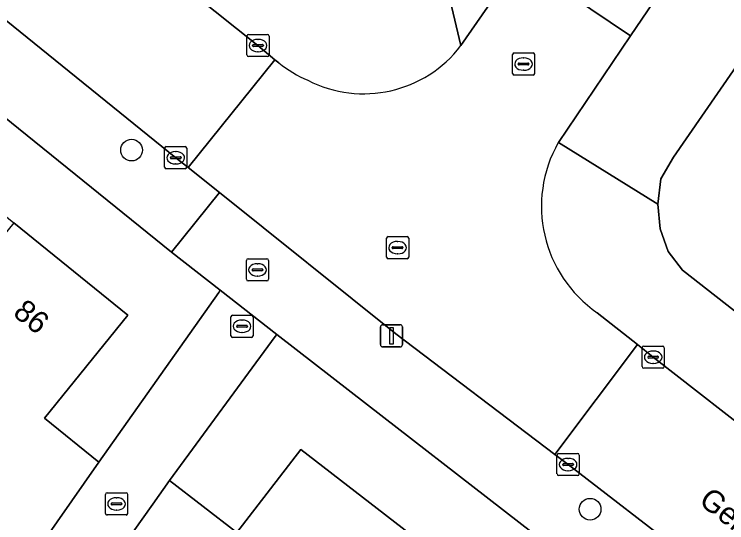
# Model space of a CAD drawing. Extents: x 160157 to 160921, y 381516 to 382045.
# Drawn here: x 160586.64 to 160618.81, y 381662.86 to 381685.82 of the extents above; entities that cross this region are included whole.
import ezdxf

# ---------------------------------------------------------------- set-up
doc = ezdxf.new("R2010")
doc.units = 0
for name, color, linetype in [('IMGEO_Boom', 7, 'Continuous'), ('IMGEO_Brandkraan', 7, 'Continuous'), ('IMGEO_Erf', 7, 'Continuous'), ('IMGEO_Kolk', 7, 'Continuous'), ('IMGEO_Lichtmast', 7, 'Continuous'), ('IMGEO_Openbare_ruimte_label', 7, 'Continuous'), ('IMGEO_Pand', 7, 'Continuous'), ('IMGEO_Pand_nummerreeks', 7, 'Continuous'), ('IMGEO_Rijbaan_lokaal_open', 7, 'Continuous'), ('IMGEO_Rioolput', 7, 'Continuous'), ('IMGEO_Voetpad_open', 7, 'Continuous')]:
    doc.layers.add(name, color=color, linetype=linetype)

msp = doc.modelspace()

# ---------------------------------------------------------------- linework, layer by layer
at = {"layer": 'IMGEO_Boom'}
for centre in [(160591.934, 381679.684), (160612.638, 381663.471)]:
    msp.add_circle(centre, 0.489, dxfattribs=at)
at = {"layer": 'IMGEO_Brandkraan'}
for p, q in [((160597.12, 381673.85), (160597.12, 381674.702)), ((160597.195, 381674.776), (160598.047, 381674.776)), ((160598.121, 381674.702), (160598.121, 381673.85)), ((160597.422, 381674.319), (160597.82, 381674.319)), ((160597.608, 381674.556), (160597.633, 381674.556)), ((160597.379, 381674.27), (160597.379, 381674.282)), ((160597.817, 381674.233), (160597.419, 381674.233)), ((160597.631, 381673.996), (160597.606, 381673.996)), ((160597.863, 381674.282), (160597.863, 381674.27)), ((160598.047, 381673.776), (160597.195, 381673.776))]:
    msp.add_line(p, q, dxfattribs=at)
for points in [[(160597.12, 381673.85), (160597.12, 381674.702)], [(160597.195, 381674.776), (160598.047, 381674.776)], [(160598.121, 381674.702), (160598.121, 381673.85)], [(160598.047, 381673.776), (160597.195, 381673.776)]]:
    msp.add_lwpolyline(points, dxfattribs=at)
for centre, radius, start, end in [((160597.197, 381674.7), 0.0765, 91.552, 178.448), ((160597.197, 381674.7), 0.0765, 91.552, 178.448), ((160598.045, 381674.7), 0.0765, 1.552, 88.448), ((160598.045, 381674.7), 0.0765, 1.552, 88.448), ((160597.419, 381674.279), 0.0403, 85.8775, 175.7526), ((160597.824, 381674.281), 0.0386, 1.7309, 96.639), ((160597.416, 381674.269), 0.0366, 178.938, 274.7102), ((160597.82, 381674.276), 0.043, 264.8664, 352.4533), ((160597.197, 381673.852), 0.0765, 181.552, 268.448), ((160597.197, 381673.852), 0.0765, 181.552, 268.448), ((160598.045, 381673.852), 0.0765, 271.552, 358.448), ((160598.045, 381673.852), 0.0765, 271.552, 358.448)]:
    msp.add_arc(centre, radius, start, end, dxfattribs=at)
for centre, major_axis, ratio, start_param, end_param in [((160597.607, 381674.276), (-0.387, 0.002), 0.722429, 4.712389, 7.853982), ((160597.632, 381674.276), (-0.39, 0.002), 0.717154, 1.570796, 4.712389)]:
    msp.add_ellipse(centre, major_axis=major_axis, ratio=ratio, start_param=start_param, end_param=end_param, dxfattribs=at)
at = {"layer": 'IMGEO_Erf'}
for points in [[(160644.455, 381719.97), (160616.408, 381679.37), (160615.835, 381678.381), (160615.694, 381677.246), (160615.808, 381676.128), (160616.155, 381675.113), (160616.813, 381674.266), (160634.918, 381660.1)], [(160652.939, 381629.15), (160652.772, 381629.282), (160601.85, 381668.749), (160598.492, 381671.366), (160598.418, 381671.265), (160593.646, 381664.765), (160596.685, 381662.418), (160599.574, 381666.16), (160604.808, 381662.117), (160609.913, 381658.174), (160615.018, 381654.231), (160620.122, 381650.288), (160625.226, 381646.346), (160630.458, 381642.305), (160628.484, 381639.75), (160630.816, 381637.948), (160632.401, 381640), (160640.628, 381633.646), (160639.436, 381632.103), (160647.232, 381626.081)]]:
    msp.add_lwpolyline(points, dxfattribs=at)
msp.add_lwpolyline([(160558.545, 381703.514), (160556.409, 381700.887), (160561.559, 381696.713), (160566.569, 381692.651), (160571.58, 381688.589), (160576.591, 381684.528), (160581.601, 381680.467), (160586.612, 381676.405), (160591.761, 381672.231), (160587.997, 381667.587), (160590.45, 381665.598), (160595.868, 381673.258), (160595.937, 381673.356), (160593.737, 381675.072)], close=True, dxfattribs=at)
at = {"layer": 'IMGEO_Kolk'}
for p, q in [((160597.141, 381683.978), (160597.141, 381684.83)), ((160597.216, 381684.904), (160598.068, 381684.904)), ((160597.629, 381684.684), (160597.654, 381684.684)), ((160598.142, 381684.83), (160598.142, 381683.978)), ((160597.4, 381684.398), (160597.4, 381684.41)), ((160597.838, 381684.361), (160597.44, 381684.361)), ((160597.443, 381684.447), (160597.841, 381684.447)), ((160597.884, 381684.41), (160597.884, 381684.398)), ((160597.652, 381684.124), (160597.627, 381684.124)), ((160598.068, 381683.904), (160597.216, 381683.904)), ((160593.427, 381678.913), (160593.427, 381679.765)), ((160593.502, 381679.839), (160594.354, 381679.839)), ((160594.428, 381679.765), (160594.428, 381678.913)), ((160593.915, 381679.619), (160593.94, 381679.619)), ((160593.686, 381679.333), (160593.686, 381679.345)), ((160594.124, 381679.296), (160593.726, 381679.296)), ((160593.729, 381679.382), (160594.127, 381679.382)), ((160594.17, 381679.345), (160594.17, 381679.333)), ((160594.354, 381678.839), (160593.502, 381678.839)), ((160593.938, 381679.059), (160593.913, 381679.059)), ((160614.987, 381669.908), (160614.987, 381670.76)), ((160615.062, 381670.834), (160615.914, 381670.834)), ((160615.988, 381670.76), (160615.988, 381669.908)), ((160615.475, 381670.614), (160615.5, 381670.614)), ((160615.246, 381670.328), (160615.246, 381670.34)), ((160615.684, 381670.291), (160615.286, 381670.291)), ((160615.289, 381670.377), (160615.687, 381670.377)), ((160615.73, 381670.34), (160615.73, 381670.328)), ((160615.914, 381669.834), (160615.062, 381669.834)), ((160615.498, 381670.054), (160615.473, 381670.054)), ((160611.217, 381665.988), (160612.069, 381665.988)), ((160611.142, 381665.062), (160611.142, 381665.914)), ((160611.63, 381665.768), (160611.655, 381665.768)), ((160612.143, 381665.914), (160612.143, 381665.062)), ((160611.401, 381665.482), (160611.401, 381665.494)), ((160611.839, 381665.445), (160611.441, 381665.445)), ((160611.444, 381665.531), (160611.842, 381665.531)), ((160611.885, 381665.494), (160611.885, 381665.482)), ((160612.069, 381664.988), (160611.217, 381664.988)), ((160611.653, 381665.208), (160611.628, 381665.208)), ((160590.756, 381663.284), (160590.756, 381664.136)), ((160590.831, 381664.21), (160591.683, 381664.21)), ((160591.757, 381664.136), (160591.757, 381663.284)), ((160591.015, 381663.704), (160591.015, 381663.716)), ((160591.058, 381663.753), (160591.456, 381663.753)), ((160591.244, 381663.99), (160591.269, 381663.99)), ((160591.499, 381663.716), (160591.499, 381663.704)), ((160591.453, 381663.667), (160591.055, 381663.667)), ((160591.267, 381663.43), (160591.242, 381663.43)), ((160591.683, 381663.21), (160590.831, 381663.21))]:
    msp.add_line(p, q, dxfattribs=at)
for points in [[(160597.141, 381683.978), (160597.141, 381684.83)], [(160597.216, 381684.904), (160598.068, 381684.904)], [(160598.142, 381684.83), (160598.142, 381683.978)], [(160598.068, 381683.904), (160597.216, 381683.904)], [(160593.427, 381678.913), (160593.427, 381679.765)], [(160593.502, 381679.839), (160594.354, 381679.839)], [(160594.428, 381679.765), (160594.428, 381678.913)], [(160594.354, 381678.839), (160593.502, 381678.839)], [(160614.987, 381669.908), (160614.987, 381670.76)], [(160615.062, 381670.834), (160615.914, 381670.834)], [(160615.988, 381670.76), (160615.988, 381669.908)], [(160615.914, 381669.834), (160615.062, 381669.834)], [(160611.217, 381665.988), (160612.069, 381665.988)], [(160611.142, 381665.062), (160611.142, 381665.914)], [(160612.143, 381665.914), (160612.143, 381665.062)], [(160612.069, 381664.988), (160611.217, 381664.988)], [(160590.756, 381663.284), (160590.756, 381664.136)], [(160590.831, 381664.21), (160591.683, 381664.21)], [(160591.757, 381664.136), (160591.757, 381663.284)], [(160591.683, 381663.21), (160590.831, 381663.21)]]:
    msp.add_lwpolyline(points, dxfattribs=at)
for centre, radius, start, end in [((160597.218, 381684.828), 0.0765, 91.552, 178.448), ((160597.218, 381684.828), 0.0765, 91.552, 178.448), ((160598.066, 381684.828), 0.0765, 1.552, 88.448), ((160598.066, 381684.828), 0.0765, 1.552, 88.448), ((160597.44, 381684.407), 0.0403, 85.8775, 175.7526), ((160597.437, 381684.397), 0.0366, 178.938, 274.7102), ((160597.841, 381684.404), 0.043, 264.8664, 352.4533), ((160597.845, 381684.409), 0.0386, 1.7309, 96.639), ((160597.218, 381683.98), 0.0765, 181.552, 268.448), ((160597.218, 381683.98), 0.0765, 181.552, 268.448), ((160598.066, 381683.98), 0.0765, 271.552, 358.448), ((160598.066, 381683.98), 0.0765, 271.552, 358.448), ((160593.504, 381679.763), 0.0765, 91.552, 178.448), ((160593.504, 381679.763), 0.0765, 91.552, 178.448), ((160594.352, 381679.763), 0.0765, 1.552, 88.448), ((160594.352, 381679.763), 0.0765, 1.552, 88.448), ((160593.726, 381679.342), 0.0403, 85.8775, 175.7526), ((160593.723, 381679.332), 0.0366, 178.938, 274.7102), ((160594.127, 381679.339), 0.043, 264.8664, 352.4533), ((160594.131, 381679.344), 0.0386, 1.7309, 96.639), ((160593.504, 381678.915), 0.0765, 181.552, 268.448), ((160593.504, 381678.915), 0.0765, 181.552, 268.448), ((160594.352, 381678.915), 0.0765, 271.552, 358.448), ((160594.352, 381678.915), 0.0765, 271.552, 358.448), ((160615.064, 381670.758), 0.0765, 91.552, 178.448), ((160615.064, 381670.758), 0.0765, 91.552, 178.448), ((160615.912, 381670.758), 0.0765, 1.552, 88.448), ((160615.912, 381670.758), 0.0765, 1.552, 88.448), ((160615.286, 381670.337), 0.0403, 85.8775, 175.7526), ((160615.283, 381670.327), 0.0366, 178.938, 274.7102), ((160615.687, 381670.334), 0.043, 264.8664, 352.4533), ((160615.691, 381670.339), 0.0386, 1.7309, 96.639), ((160615.064, 381669.91), 0.0765, 181.552, 268.448), ((160615.064, 381669.91), 0.0765, 181.552, 268.448), ((160615.912, 381669.91), 0.0765, 271.552, 358.448), ((160615.912, 381669.91), 0.0765, 271.552, 358.448), ((160611.219, 381665.912), 0.0765, 91.552, 178.448), ((160611.219, 381665.912), 0.0765, 91.552, 178.448), ((160612.067, 381665.912), 0.0765, 1.552, 88.448), ((160612.067, 381665.912), 0.0765, 1.552, 88.448), ((160611.441, 381665.491), 0.0403, 85.8775, 175.7526), ((160611.438, 381665.481), 0.0366, 178.938, 274.7102), ((160611.842, 381665.488), 0.043, 264.8664, 352.4533), ((160611.846, 381665.493), 0.0386, 1.7309, 96.639), ((160611.219, 381665.064), 0.0765, 181.552, 268.448), ((160611.219, 381665.064), 0.0765, 181.552, 268.448), ((160612.067, 381665.064), 0.0765, 271.552, 358.448), ((160612.067, 381665.064), 0.0765, 271.552, 358.448), ((160590.833, 381664.134), 0.0765, 91.552, 178.448), ((160590.833, 381664.134), 0.0765, 91.552, 178.448), ((160591.681, 381664.134), 0.0765, 1.552, 88.448), ((160591.681, 381664.134), 0.0765, 1.552, 88.448), ((160591.055, 381663.713), 0.0403, 85.8775, 175.7526), ((160591.052, 381663.703), 0.0366, 178.938, 274.7102), ((160591.456, 381663.71), 0.043, 264.8664, 352.4533), ((160591.46, 381663.715), 0.0386, 1.7309, 96.639), ((160590.833, 381663.286), 0.0765, 181.552, 268.448), ((160590.833, 381663.286), 0.0765, 181.552, 268.448), ((160591.681, 381663.286), 0.0765, 271.552, 358.448), ((160591.681, 381663.286), 0.0765, 271.552, 358.448)]:
    msp.add_arc(centre, radius, start, end, dxfattribs=at)
for centre, major_axis, ratio, start_param, end_param in [((160597.628, 381684.404), (-0.387, 0.002), 0.722429, 4.712389, 7.853982), ((160597.653, 381684.404), (-0.39, 0.002), 0.717154, 1.570796, 4.712389), ((160593.914, 381679.339), (-0.387, 0.002), 0.722429, 4.712389, 7.853982), ((160593.939, 381679.339), (-0.39, 0.002), 0.717154, 1.570796, 4.712389), ((160615.474, 381670.334), (-0.387, 0.002), 0.722429, 4.712389, 7.853982), ((160615.499, 381670.334), (-0.39, 0.002), 0.717154, 1.570796, 4.712389), ((160611.629, 381665.488), (-0.387, 0.002), 0.722429, 4.712389, 7.853982), ((160611.654, 381665.488), (-0.39, 0.002), 0.717154, 1.570796, 4.712389), ((160591.243, 381663.71), (-0.387, 0.002), 0.722429, 4.712389, 7.853982), ((160591.268, 381663.71), (-0.39, 0.002), 0.717154, 1.570796, 4.712389)]:
    msp.add_ellipse(centre, major_axis=major_axis, ratio=ratio, start_param=start_param, end_param=end_param, dxfattribs=at)
at = {"layer": 'IMGEO_Lichtmast'}
for p, q in [((160603.27, 381671.8), (160604.06, 381671.8)), ((160604.06, 381671.8), (160603.27, 381671.8)), ((160603.17, 381670.9), (160603.17, 381671.7)), ((160603.17, 381671.7), (160603.17, 381670.9)), ((160604.16, 381671.7), (160604.16, 381670.9)), ((160604.16, 381670.9), (160604.16, 381671.7)), ((160604.06, 381670.8), (160603.27, 381670.8)), ((160603.27, 381670.8), (160604.06, 381670.8))]:
    msp.add_line(p, q, dxfattribs=at)
msp.add_lwpolyline([(160603.59, 381671.675), (160603.74, 381671.675), (160603.74, 381670.925), (160603.59, 381670.925), (160603.59, 381671.675)], dxfattribs=at)
for centre, start, end in [((160603.27, 381671.7), 90, 180), ((160603.27, 381671.7), 90, 180), ((160604.06, 381671.7), 0, 90), ((160604.06, 381671.7), 360, 90), ((160603.27, 381670.9), 180, 270), ((160603.27, 381670.9), 180, 270), ((160604.06, 381670.9), 270, 0), ((160604.06, 381670.9), 270, 0)]:
    msp.add_arc(centre, 0.1, start, end, dxfattribs=at)
at = {"layer": 'IMGEO_Pand'}
for points in [[(160580.438, 381668.789), (160582.556, 381667.072), (160582.916, 381667.516), (160585.732, 381665.217), (160583.705, 381662.628), (160586.695, 381660.204), (160590.45, 381665.598), (160587.997, 381667.587), (160591.761, 381672.231), (160586.612, 381676.405)], [(160604.808, 381662.117), (160599.574, 381666.16), (160596.685, 381662.418), (160593.646, 381664.765), (160592.891, 381663.696), (160589.08, 381658.343), (160588.551, 381657.587), (160593.872, 381653.476), (160596.57, 381656.969), (160599.239, 381654.908)]]:
    msp.add_lwpolyline(points, close=True, dxfattribs=at)
at = {"layer": 'IMGEO_Rijbaan_lokaal_open'}
for points in [[(160678.334, 381788.56), (160651.806, 381750), (160643.136, 381737.367), (160641.13, 381734.448), (160614.441, 381695.549), (160610.996, 381690.462), (160609.452, 381688.229), (160609.962, 381687.883), (160614.454, 381684.835), (160615.999, 381687.121), (160619.05, 381691.582), (160640.187, 381722.521), (160642.496, 381725.9), (160658.96, 381750), (160667.503, 381762.414)], [(160614.454, 381684.835), (160609.962, 381687.883), (160609.452, 381688.229), (160606.806, 381684.4)], [(160611.203, 381680.025), (160614.454, 381684.835)], [(160598.577, 381683.621), (160598.404, 381683.766), (160594.486, 381678.894), (160595.897, 381677.768), (160603.873, 381671.389), (160611.044, 381665.943), (160614.775, 381670.9), (160612.96, 381672.341)], [(160589.08, 381658.343), (160592.891, 381663.696), (160593.646, 381664.765), (160598.418, 381671.265), (160598.492, 381671.366), (160595.937, 381673.356), (160595.868, 381673.258), (160590.45, 381665.598), (160586.695, 381660.204)]]:
    msp.add_lwpolyline(points, dxfattribs=at)
for points in [[(160568.758, 381707.591), (160557.554, 381716.59), (160557.502, 381716.634), (160557.472, 381716.661), (160550.945, 381722.011), (160550.931, 381722.022), (160550.918, 381722.034), (160550.145, 381722.678), (160546.247, 381717.93), (160547.02, 381717.298), (160547.066, 381717.257), (160553.47, 381712.091), (160558.948, 381707.655), (160565.145, 381702.637), (160577.959, 381692.258), (160593.928, 381679.339), (160594.486, 381678.894), (160598.404, 381683.766), (160597.642, 381684.404), (160592.745, 381688.322), (160581.553, 381697.274)], [(160637.757, 381653.019), (160629.795, 381659.181), (160625.991, 381662.142), (160615.488, 381670.334), (160614.775, 381670.9), (160611.044, 381665.943), (160611.643, 381665.488), (160622.338, 381657.247), (160634.337, 381647.947), (160640.783, 381642.937), (160653.969, 381632.702), (160654.563, 381632.216), (160655.367, 381631.558), (160659.031, 381636.532), (160658.192, 381637.172), (160657.666, 381637.573), (160640.627, 381650.806)]]:
    msp.add_lwpolyline(points, close=True, dxfattribs=at)
for centre, radius, start, end in [((160602.412, 381687.757), 5.53, 242.9032, 322.6244), ((160602.286, 381688.33), 5.995, 231.7715, 246.4676), ((160616.274, 381677.142), 5.834, 150.3803, 235.379)]:
    msp.add_arc(centre, radius, start, end, dxfattribs=at)
at = {"layer": 'IMGEO_Rioolput'}
for p, q in [((160609.133, 381683.144), (160609.133, 381683.996)), ((160609.208, 381684.07), (160610.06, 381684.07)), ((160610.134, 381683.996), (160610.134, 381683.144)), ((160609.621, 381683.85), (160609.646, 381683.85)), ((160609.392, 381683.564), (160609.392, 381683.576)), ((160609.83, 381683.527), (160609.432, 381683.527)), ((160609.435, 381683.613), (160609.833, 381683.613)), ((160609.876, 381683.576), (160609.876, 381683.564)), ((160610.06, 381683.07), (160609.208, 381683.07)), ((160609.644, 381683.29), (160609.619, 381683.29)), ((160603.444, 381674.854), (160603.444, 381675.706)), ((160603.519, 381675.78), (160604.371, 381675.78)), ((160604.445, 381675.706), (160604.445, 381674.854)), ((160603.703, 381675.274), (160603.703, 381675.286)), ((160603.746, 381675.323), (160604.144, 381675.323)), ((160603.932, 381675.56), (160603.957, 381675.56)), ((160604.187, 381675.286), (160604.187, 381675.274)), ((160604.141, 381675.237), (160603.743, 381675.237)), ((160603.955, 381675), (160603.93, 381675)), ((160604.371, 381674.78), (160603.519, 381674.78)), ((160596.421, 381671.304), (160596.421, 381672.156)), ((160596.496, 381672.23), (160597.348, 381672.23)), ((160597.422, 381672.156), (160597.422, 381671.304)), ((160596.68, 381671.724), (160596.68, 381671.736)), ((160596.723, 381671.773), (160597.121, 381671.773)), ((160596.909, 381672.01), (160596.934, 381672.01)), ((160597.164, 381671.736), (160597.164, 381671.724)), ((160597.118, 381671.687), (160596.72, 381671.687)), ((160596.932, 381671.45), (160596.907, 381671.45)), ((160597.348, 381671.23), (160596.496, 381671.23))]:
    msp.add_line(p, q, dxfattribs=at)
for points in [[(160609.133, 381683.144), (160609.133, 381683.996)], [(160609.208, 381684.07), (160610.06, 381684.07)], [(160610.134, 381683.996), (160610.134, 381683.144)], [(160610.06, 381683.07), (160609.208, 381683.07)], [(160603.444, 381674.854), (160603.444, 381675.706)], [(160603.519, 381675.78), (160604.371, 381675.78)], [(160604.445, 381675.706), (160604.445, 381674.854)], [(160604.371, 381674.78), (160603.519, 381674.78)], [(160596.421, 381671.304), (160596.421, 381672.156)], [(160596.496, 381672.23), (160597.348, 381672.23)], [(160597.422, 381672.156), (160597.422, 381671.304)], [(160597.348, 381671.23), (160596.496, 381671.23)]]:
    msp.add_lwpolyline(points, dxfattribs=at)
for centre, radius, start, end in [((160609.21, 381683.994), 0.0765, 91.552, 178.448), ((160609.21, 381683.994), 0.0765, 91.552, 178.448), ((160610.058, 381683.994), 0.0765, 1.552, 88.448), ((160610.058, 381683.994), 0.0765, 1.552, 88.448), ((160609.432, 381683.573), 0.0403, 85.8775, 175.7526), ((160609.429, 381683.563), 0.0366, 178.938, 274.7102), ((160609.833, 381683.57), 0.043, 264.8664, 352.4533), ((160609.837, 381683.575), 0.0386, 1.7309, 96.639), ((160609.21, 381683.146), 0.0765, 181.552, 268.448), ((160609.21, 381683.146), 0.0765, 181.552, 268.448), ((160610.058, 381683.146), 0.0765, 271.552, 358.448), ((160610.058, 381683.146), 0.0765, 271.552, 358.448), ((160603.521, 381675.704), 0.0765, 91.552, 178.448), ((160603.521, 381675.704), 0.0765, 91.552, 178.448), ((160604.369, 381675.704), 0.0765, 1.552, 88.448), ((160604.369, 381675.704), 0.0765, 1.552, 88.448), ((160603.743, 381675.283), 0.0403, 85.8775, 175.7526), ((160603.74, 381675.273), 0.0366, 178.938, 274.7102), ((160604.144, 381675.28), 0.043, 264.8664, 352.4533), ((160604.148, 381675.285), 0.0386, 1.7309, 96.639), ((160603.521, 381674.856), 0.0765, 181.552, 268.448), ((160603.521, 381674.856), 0.0765, 181.552, 268.448), ((160604.369, 381674.856), 0.0765, 271.552, 358.448), ((160604.369, 381674.856), 0.0765, 271.552, 358.448), ((160596.498, 381672.154), 0.0765, 91.552, 178.448), ((160596.498, 381672.154), 0.0765, 91.552, 178.448), ((160597.346, 381672.154), 0.0765, 1.552, 88.448), ((160597.346, 381672.154), 0.0765, 1.552, 88.448), ((160596.72, 381671.733), 0.0403, 85.8775, 175.7526), ((160596.717, 381671.723), 0.0366, 178.938, 274.7102), ((160597.121, 381671.73), 0.043, 264.8664, 352.4533), ((160597.125, 381671.735), 0.0386, 1.7309, 96.639), ((160596.498, 381671.306), 0.0765, 181.552, 268.448), ((160596.498, 381671.306), 0.0765, 181.552, 268.448), ((160597.346, 381671.306), 0.0765, 271.552, 358.448), ((160597.346, 381671.306), 0.0765, 271.552, 358.448)]:
    msp.add_arc(centre, radius, start, end, dxfattribs=at)
for centre, major_axis, ratio, start_param, end_param in [((160609.62, 381683.57), (-0.387, 0.002), 0.722429, 4.712389, 7.853982), ((160609.645, 381683.57), (-0.39, 0.002), 0.717154, 1.570796, 4.712389), ((160603.931, 381675.28), (-0.387, 0.002), 0.722429, 4.712389, 7.853982), ((160603.956, 381675.28), (-0.39, 0.002), 0.717154, 1.570796, 4.712389), ((160596.908, 381671.73), (-0.387, 0.002), 0.722429, 4.712389, 7.853982), ((160596.933, 381671.73), (-0.39, 0.002), 0.717154, 1.570796, 4.712389)]:
    msp.add_ellipse(centre, major_axis=major_axis, ratio=ratio, start_param=start_param, end_param=end_param, dxfattribs=at)
at = {"layer": 'IMGEO_Voetpad_open'}
for points in [[(160707.501, 381830.956), (160711.08, 381836.076), (160711.248, 381836.325), (160707.078, 381835.076), (160693.176, 381814.897), (160692.079, 381813.304), (160675.928, 381789.86), (160675.328, 381788.989), (160648.467, 381750), (160641.671, 381740.128), (160640.592, 381738.561), (160605.905, 381688.17), (160606.806, 381684.4), (160609.452, 381688.229), (160610.996, 381690.462), (160614.441, 381695.549), (160641.13, 381734.448), (160643.136, 381737.367), (160651.806, 381750), (160678.334, 381788.56), (160680.332, 381791.464), (160692.328, 381808.901), (160699.651, 381819.545)], [(160603.873, 381671.389), (160595.897, 381677.768), (160593.737, 381675.072), (160595.937, 381673.356), (160598.492, 381671.366), (160601.85, 381668.749), (160652.772, 381629.282), (160652.939, 381629.15), (160655.367, 381631.558), (160654.563, 381632.216), (160653.969, 381632.702), (160640.783, 381642.937), (160634.337, 381647.947), (160622.338, 381657.247), (160611.643, 381665.488), (160611.044, 381665.943)]]:
    msp.add_lwpolyline(points, close=True, dxfattribs=at)
for points in [[(160716.089, 381833.009), (160716.028, 381832.837), (160712.504, 381827.801), (160703.573, 381814.824), (160700.524, 381810.394), (160670.296, 381766.471), (160667.503, 381762.414), (160658.96, 381750), (160642.496, 381725.9), (160640.187, 381722.521), (160619.05, 381691.582), (160615.999, 381687.121), (160614.454, 381684.835), (160611.203, 381680.025), (160615.694, 381677.246), (160615.835, 381678.381), (160616.408, 381679.37), (160644.455, 381719.97), (160645.316, 381721.217), (160665.2, 381750)], [(160557.472, 381716.661), (160557.502, 381716.634), (160557.554, 381716.59), (160568.758, 381707.591), (160581.553, 381697.274), (160592.745, 381688.322), (160597.642, 381684.404), (160598.404, 381683.766), (160598.577, 381683.621)], [(160558.545, 381703.514), (160593.737, 381675.072), (160595.897, 381677.768), (160594.486, 381678.894), (160593.928, 381679.339), (160577.959, 381692.258)], [(160606.806, 381684.4), (160605.905, 381688.17)], [(160616.813, 381674.266), (160616.155, 381675.113), (160615.808, 381676.128), (160615.694, 381677.246), (160611.203, 381680.025)], [(160612.96, 381672.341), (160614.775, 381670.9), (160615.488, 381670.334), (160625.991, 381662.142), (160629.795, 381659.181), (160637.757, 381653.019), (160640.627, 381650.806), (160657.666, 381637.573), (160658.192, 381637.172), (160659.031, 381636.532), (160661.788, 381640.317), (160660.576, 381640.417), (160659.494, 381640.87), (160636.475, 381658.882), (160634.918, 381660.1), (160616.813, 381674.266)]]:
    msp.add_lwpolyline(points, dxfattribs=at)
for centre, radius, start, end in [((160602.412, 381687.757), 5.53, 242.9032, 322.6244), ((160602.286, 381688.33), 5.995, 231.7715, 246.4676), ((160616.274, 381677.142), 5.834, 150.3803, 235.379)]:
    msp.add_arc(centre, radius, start, end, dxfattribs=at)

# ---------------------------------------------------------------- texts
at = {"layer": 'IMGEO_Openbare_ruimte_label'}
msp.add_text('Genneperweg', height=1, rotation=321.698, dxfattribs=at).set_placement((160617.494, 381663.75))
at = {"layer": 'IMGEO_Pand_nummerreeks'}
msp.add_text('86', height=1, rotation=320.9721, dxfattribs=at).set_placement((160586.529, 381672.25))

doc.saveas('drawing.dxf')
